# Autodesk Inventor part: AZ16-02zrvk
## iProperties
Created: 2006-08
Part Number: AZ16-02zrvk
Material: Kst - PE/UHMW - Schwarz
Description: Sicherheitsschalter
Document SubType Name: Modellieren
Designer: TMT
Manufacturer: Standard
Standards Organization: Custom
Author: TMT
Comments: SCHMERSAL
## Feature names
1. Basis1
